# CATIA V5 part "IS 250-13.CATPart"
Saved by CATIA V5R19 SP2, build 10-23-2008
Part number: IS 250-13
Bounding box of the stored display mesh (mm): x -18.951 to 18.951, y -18.952 to 18.952, z 0 to 75.4
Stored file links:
  C:\Users\Bora\Desktop\3D Katı model\IS serisi\IS 250\IS 250-13.CATPart
  C:\Program Files\Dassault Systemes\B19\intel_a\reffiles\standard\MetricThickPitch.txt
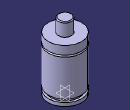
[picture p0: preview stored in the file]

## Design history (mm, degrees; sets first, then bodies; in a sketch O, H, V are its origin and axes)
Body1 (main body)
  Sketch1 on yz-plane, origin (0, 0, 0), H (0, 1, 0), V (0, 0, 1)
    point P3 (7.5, 74.4)
    point P5 (7.5, 74.4)
    point P7 (19, 50.9)
    point P8 (19, 48.9)
    point P12 (19, 48.9)
    point P13 (19, 50.9)
    line L1 (19, 0) -> (19, 4)
    line L2 (7.5, 74.4) -> (7.5, 60.4)
    arc A1 centre (6.5, 74.4) radius 1 from (7.5, 74.4) to (6.5, 75.4) ccw
    arc A2 centre (19, 49.9) radius 1 from (19, 50.9) to (19, 48.9) ccw
    line L3 (16.5, 7.5) -> (16.5, 4)
    line L4 (19, 7.5) -> (19, 48.9)
    line L5 (19, 50.9) -> (19, 60.4)
    line L6 (6.5, 75.4) -> (0, 75.4)
    point P15 (0, 75.4)
    line L7 (7.5, 60.4) -> (19, 60.4)
    line L8 (16.5, 7.5) -> (19, 7.5)
    line L9 (16.5, 4) -> (19, 4)
    line L10 (0, 0) -> (19, 0)
    tangency: L6 A1
    coincidence: P15 V, P3 P5, P7 P13, P8 P12
    horizontal: L7 H, L8 H, L9 H, L10 H
  Shaft1: profile Sketch1, axis Sketch1.V, angle 360
  Sketch2 on face of Shaft1 from Sketch1.L10, origin (0, 0, 0), H (1, 0, 0), V (0, -1, 0)
    point P1 (0, 0)
  Hole1: placed by Sketch2, at (0, 0, 0) direction (0, 0, 1), diameter 6.647, depth 7, threaded "M8", thread diameter 8, thread depth 7, pitch 1.25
